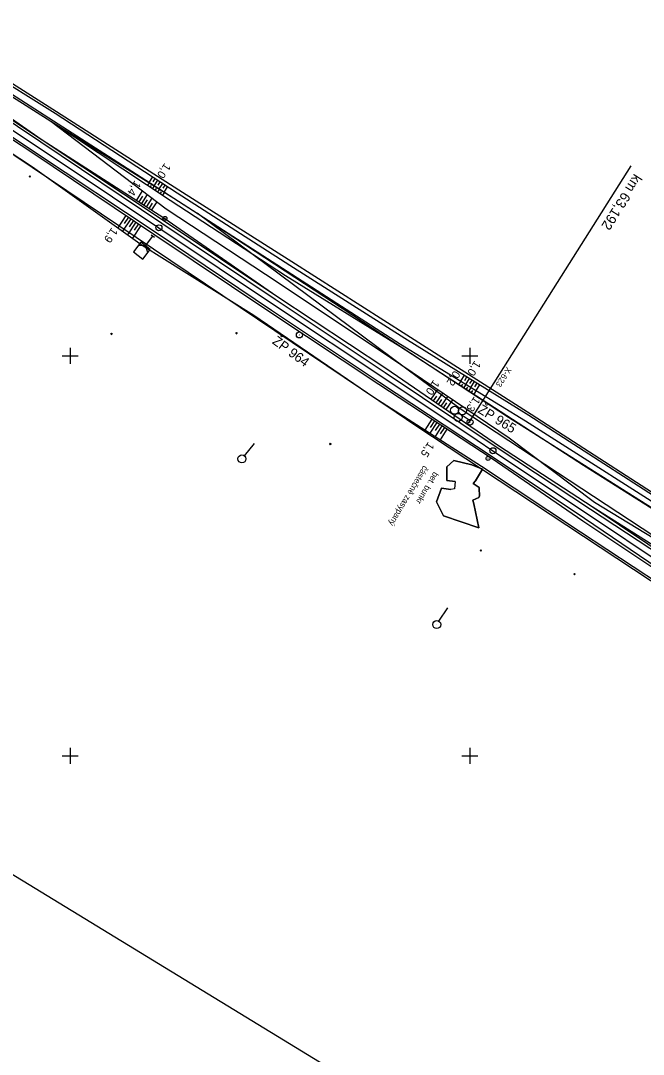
# Model space of a CAD drawing. Extents: x -804899 to -803847, y -1165742 to -1164942.
# Drawn here: x -804512.4 to -804356.6, y -1165474.6 to -1165216.2 of the extents above; entities that cross this region are included whole.
import ezdxf

# ---------------------------------------------------------------- set-up
doc = ezdxf.new("R2010")
doc.units = 0
for name, color, linetype in [('0381KM061-064P - Vrstva 1', 7, 'Continuous'), ('0381KM061-064P - Vrstva 23', 7, 'Continuous'), ('0381KM061-064P - Vrstva 36', 7, 'Continuous'), ('0381KM061-064P - Vrstva 4', 7, 'Continuous'), ('0381KM061-064P - Vrstva 48', 7, 'Continuous'), ('0381KM061-064P - Vrstva 49', 7, 'Continuous'), ('0381KM061-064P - Vrstva 51', 7, 'Continuous'), ('0381KM061-064P - Vrstva 55', 7, 'Continuous'), ('0381KM061-064P - Vrstva 7', 7, 'Continuous'), ('0381KM061-064P - Vrstva 8', 7, 'Continuous'), ('formát', 7, 'Continuous'), ('hran DP - hran DP', 7, 'Continuous'), ('krizky_1000 - Vrstva 1', 7, 'Continuous'), ('vyt_sit - stávající', 7, 'Continuous')]:
    doc.layers.add(name, color=color, linetype=linetype)

msp = doc.modelspace()

# ---------------------------------------------------------------- linework, layer by layer
at = {"layer": '0381KM061-064P - Vrstva 1'}
msp.add_lwpolyline([(-804619.36, -1165173.74), (-804594.78, -1165190.05), (-804577, -1165201.91), (-804561.16, -1165212.47), (-804538.32, -1165227.67), (-804515.3, -1165243.02), (-804489.41, -1165260.27), (-804477.81, -1165268), (-804447.6, -1165288.14), (-804422.03, -1165305.2), (-804398.19, -1165321.09), (-804394.24, -1165323.73), (-804371.85, -1165338.65), (-804349.9, -1165353.29), (-804326.64, -1165368.8), (-804303.84, -1165384.01), (-804280.33, -1165399.7), (-804257.04, -1165415.23), (-804233.85, -1165430.69)], dxfattribs=at)
at = {"layer": '0381KM061-064P - Vrstva 23'}
msp.add_lwpolyline([(-804404.03, -1165326.13), (-804405.8, -1165327.74), (-804405.76, -1165331.16), (-804403.73, -1165331.39), (-804403.83, -1165333.25), (-804404.81, -1165333.4), (-804407.08, -1165333.06), (-804408.38, -1165336.47), (-804406.6, -1165340), (-804397.73, -1165342.97), (-804399.04, -1165336.98), (-804399.28, -1165336.09), (-804397.81, -1165335.38), (-804397.64, -1165335), (-804397.65, -1165333.2), (-804397.7, -1165332.91), (-804399.15, -1165331.95), (-804398.58, -1165331.24), (-804396.84, -1165328.29), (-804399.49, -1165327.23), (-804404.03, -1165326.13)], dxfattribs=at)
at = {"layer": '0381KM061-064P - Vrstva 36'}
for p, q in [((-804456.41, -1165324.98), (-804453.88, -1165321.88)), ((-804457.04, -1165325.75), (-804457.04, -1165325.75)), ((-804407.75, -1165366.33), (-804405.5, -1165363.02)), ((-804408.31, -1165367.16), (-804408.31, -1165367.16))]:
    msp.add_line(p, q, dxfattribs=at)
for centre in [(-804457.04, -1165325.75), (-804408.31, -1165367.16)]:
    msp.add_circle(centre, 1, dxfattribs=at)
at = {"layer": '0381KM061-064P - Vrstva 4'}
for points in [[(-804755.73, -1165115.93), (-804748.17, -1165116.91), (-804721.25, -1165123.25), (-804698.66, -1165130.22), (-804681.33, -1165136.99), (-804671.47, -1165141.65), (-804648.84, -1165153.36), (-804638.11, -1165160.03), (-804624.48, -1165168.7), (-804602.56, -1165183.07), (-804574.47, -1165201.72), (-804542.72, -1165222.84), (-804507.36, -1165246.55), (-804477.08, -1165266.82), (-804448.75, -1165285.88), (-804421.18, -1165304.15), (-804392.89, -1165323.09), (-804369.85, -1165338.37), (-804348.86, -1165352.04), (-804325.13, -1165367.98), (-804299.32, -1165385.27), (-804266.05, -1165407.31), (-804234.28, -1165428.6)], [(-804755.73, -1165115.93), (-804748.03, -1165116.49), (-804721.05, -1165122.36), (-804698.44, -1165129.77), (-804680.98, -1165136.5), (-804671.21, -1165140.89), (-804648.42, -1165152.46), (-804637.55, -1165159.43), (-804624.04, -1165168.29), (-804602.25, -1165182.38), (-804573.74, -1165201.2), (-804542.46, -1165222.56), (-804507.06, -1165246.03), (-804476.47, -1165266.24), (-804448.31, -1165285.08), (-804421.02, -1165303.1), (-804392.59, -1165322.59), (-804369.41, -1165337.65), (-804348.68, -1165351.59), (-804324.76, -1165367.42), (-804298.9, -1165384.42), (-804265.65, -1165406.5), (-804234.05, -1165428.04)], [(-804626.64, -1165171.43), (-804605.18, -1165186.34), (-804576.91, -1165204.69), (-804544.69, -1165226.09), (-804509.35, -1165249.3), (-804478.87, -1165269.77), (-804450.06, -1165288.98), (-804422.82, -1165307.11), (-804394.42, -1165325.66), (-804371.77, -1165341.24), (-804350.46, -1165355.38), (-804326.73, -1165371.34), (-804301.47, -1165388.34), (-804268.3, -1165410.72), (-804235.74, -1165432.01)], [(-804576.36, -1165204.15), (-804544.19, -1165225.52), (-804508.95, -1165249), (-804478.52, -1165269.18), (-804449.67, -1165288.56), (-804422.62, -1165306.58), (-804394.22, -1165325.33), (-804371.37, -1165340.61), (-804350.54, -1165354.66), (-804326.31, -1165370.81), (-804300.9, -1165387.72), (-804267.8, -1165409.92), (-804235.52, -1165431.44)]]:
    msp.add_lwpolyline(points, dxfattribs=at)
at = {"layer": '0381KM061-064P - Vrstva 48'}
for p, q in [((-804480.29, -1165256.71), (-804479.34, -1165255.26)), ((-804479.28, -1165256.53), (-804478.71, -1165255.67)), ((-804479.02, -1165257.51), (-804478.08, -1165256.08)), ((-804478.01, -1165257.34), (-804477.46, -1165256.49)), ((-804481.97, -1165258.76), (-804483.45, -1165261.08)), ((-804480.25, -1165256.74), (-804480.67, -1165257.37)), ((-804479.78, -1165257.4), (-804480.04, -1165257.79)), ((-804478.97, -1165257.53), (-804479.42, -1165258.2)), ((-804478.52, -1165258.2), (-804478.79, -1165258.61)), ((-804477.7, -1165258.33), (-804478.16, -1165259.03)), ((-804477.74, -1165258.3), (-804476.83, -1165256.9)), ((-804477.25, -1165259.01), (-804477.54, -1165259.44)), ((-804476.43, -1165259.12), (-804476.91, -1165259.86)), ((-804476.74, -1165258.14), (-804476.2, -1165257.3)), ((-804476.47, -1165259.09), (-804475.57, -1165257.71)), ((-804481.95, -1165260.12), (-804482.82, -1165261.48)), ((-804480.77, -1165259.67), (-804482.18, -1165261.89)), ((-804480.72, -1165260.99), (-804481.55, -1165262.29)), ((-804479.57, -1165260.57), (-804480.92, -1165262.69)), ((-804478.37, -1165261.48), (-804479.66, -1165263.5)), ((-804479.5, -1165261.86), (-804480.29, -1165263.1)), ((-804486.06, -1165264.95), (-804488.11, -1165268)), ((-804484.82, -1165265.78), (-804486.89, -1165268.87)), ((-804485.44, -1165265.36), (-804486.47, -1165266.9)), ((-804483.57, -1165266.62), (-804485.67, -1165269.74)), ((-804484.19, -1165266.2), (-804485.24, -1165267.75)), ((-804482.32, -1165267.45), (-804484.45, -1165270.61)), ((-804482.95, -1165267.04), (-804484, -1165268.61)), ((-804402.3, -1165306.36), (-804401.37, -1165304.86)), ((-804401.29, -1165306.16), (-804400.73, -1165305.26)), ((-804401.02, -1165307.14), (-804400.09, -1165305.66)), ((-804402.31, -1165306.35), (-804402.82, -1165307.15)), ((-804401.88, -1165307.07), (-804402.19, -1165307.55)), ((-804401.03, -1165307.14), (-804401.56, -1165307.96)), ((-804400.6, -1165307.87), (-804400.93, -1165308.37)), ((-804399.75, -1165307.92), (-804400.3, -1165308.78)), ((-804400.01, -1165306.94), (-804399.46, -1165306.05)), ((-804399.74, -1165307.93), (-804398.82, -1165306.45)), ((-804398.73, -1165307.73), (-804398.18, -1165306.84)), ((-804398.46, -1165308.71), (-804397.55, -1165307.24)), ((-804409.69, -1165310.87), (-804408.04, -1165308.45)), ((-804409.07, -1165311.29), (-804408.24, -1165310.08)), ((-804408.45, -1165311.72), (-804406.79, -1165309.3)), ((-804407.22, -1165312.57), (-804405.55, -1165310.14)), ((-804399.33, -1165308.66), (-804399.67, -1165309.19)), ((-804398.47, -1165308.71), (-804399.04, -1165309.59)), ((-804407.84, -1165312.14), (-804407, -1165310.93)), ((-804406.6, -1165312.99), (-804405.76, -1165311.77)), ((-804405.98, -1165313.41), (-804404.31, -1165310.98)), ((-804411.18, -1165318.55), (-804409.42, -1165315.86)), ((-804409.92, -1165319.36), (-804408.16, -1165316.68)), ((-804409.84, -1165317.89), (-804408.79, -1165316.27)), ((-804408.65, -1165320.17), (-804406.91, -1165317.5)), ((-804408.58, -1165318.7), (-804407.54, -1165317.09)), ((-804407.39, -1165320.98), (-804405.65, -1165318.32)), ((-804407.32, -1165319.51), (-804406.28, -1165317.91))]:
    msp.add_line(p, q, dxfattribs=at)
at = {"layer": '0381KM061-064P - Vrstva 49'}
for p, q in [((-804509.94, -1165255.38), (-804510.3, -1165255.03)), ((-804509.94, -1165255.03), (-804510.3, -1165255.38)), ((-804489.49, -1165294.74), (-804489.84, -1165294.38)), ((-804489.49, -1165294.38), (-804489.84, -1165294.74)), ((-804458.23, -1165294.57), (-804458.58, -1165294.21)), ((-804458.23, -1165294.21), (-804458.58, -1165294.57)), ((-804434.74, -1165322.21), (-804435.09, -1165321.86)), ((-804434.74, -1165321.86), (-804435.09, -1165322.21)), ((-804397.06, -1165348.83), (-804397.41, -1165348.47)), ((-804397.06, -1165348.47), (-804397.41, -1165348.83)), ((-804373.68, -1165354.74), (-804374.04, -1165354.39)), ((-804373.68, -1165354.39), (-804374.04, -1165354.74))]:
    msp.add_line(p, q, dxfattribs=at)
for points in [[(-804668.09, -1165135.13), (-804646.08, -1165148.91), (-804635.34, -1165155.79), (-804621.98, -1165164.4), (-804599.68, -1165178.86), (-804570.23, -1165197.63), (-804539.04, -1165217.4), (-804503.79, -1165239.32), (-804473.21, -1165259.25), (-804445.02, -1165277.37), (-804416.3, -1165295.6), (-804385.23, -1165314.87), (-804342.84, -1165342.16), (-804322.16, -1165355.5), (-804292.15, -1165374.6), (-804262.58, -1165393.44), (-804234.25, -1165411.43)], [(-804668.53, -1165136.56), (-804646.51, -1165150.38), (-804635.75, -1165157.19), (-804622.88, -1165165.28), (-804600.74, -1165180), (-804571.06, -1165199.05), (-804539.91, -1165219.23), (-804504.85, -1165241.38), (-804474.07, -1165260.59), (-804445.75, -1165278.86), (-804417.38, -1165297.08), (-804386.13, -1165316.29), (-804343.68, -1165343.22), (-804323.05, -1165356.81), (-804293.41, -1165375.48), (-804263.45, -1165394.43), (-804234.68, -1165412.78)], [(-804651.73, -1165158.22), (-804641.24, -1165165.82), (-804629.21, -1165174.28), (-804606.38, -1165188.59), (-804578.69, -1165207.38), (-804546.55, -1165228.41), (-804509.4, -1165252.77), (-804482.02, -1165272.35), (-804454.07, -1165289.87), (-804424.02, -1165310.32)], [(-804621.79, -1165169), (-804602.1, -1165181.9), (-804573.29, -1165200.8), (-804541.65, -1165222.05), (-804507.06, -1165246.03), (-804476.55, -1165265.48), (-804448.31, -1165285.08)], [(-804576.91, -1165204.69), (-804544.69, -1165226.09), (-804509.35, -1165249.3), (-804478.87, -1165269.77), (-804450.06, -1165288.98), (-804422.82, -1165307.11), (-804394.42, -1165325.66), (-804371.77, -1165341.24), (-804350.46, -1165355.38), (-804326.73, -1165371.34), (-804301.47, -1165388.34), (-804268.3, -1165410.72), (-804235.74, -1165432.01)], [(-804504.85, -1165241.38), (-804475.98, -1165263.3)], [(-804504.85, -1165241.38), (-804474.97, -1165261.14)], [(-804474.97, -1165261.14), (-804446.16, -1165279.93), (-804417.55, -1165297.62), (-804371.56, -1165327.37), (-804344.89, -1165344.14), (-804323.3, -1165357.63), (-804293.83, -1165376.15), (-804263.84, -1165395.04), (-804235.23, -1165413.58)], [(-804475.98, -1165263.3), (-804448.01, -1165281.64), (-804419.88, -1165300.43), (-804390.2, -1165320.54), (-804368.79, -1165336.61), (-804347.55, -1165349.48), (-804323.92, -1165365.2), (-804298.45, -1165381.67), (-804264.49, -1165403.75), (-804232.5, -1165426.01)], [(-804448.31, -1165285.08), (-804421.02, -1165303.1), (-804392.59, -1165322.59), (-804369.41, -1165337.65)], [(-804424.02, -1165310.32), (-804397.08, -1165327.6), (-804372.3, -1165344.03), (-804352.55, -1165356.96), (-804329.59, -1165372.88)], [(-804403.73, -1165331.39), (-804405.76, -1165331.16), (-804405.8, -1165327.74), (-804404.03, -1165326.13), (-804399.49, -1165327.23), (-804396.84, -1165328.29), (-804398.58, -1165331.24)], [(-804403.73, -1165331.39), (-804403.83, -1165333.25), (-804404.81, -1165333.4)], [(-804398.58, -1165331.24), (-804399.15, -1165331.95), (-804397.7, -1165332.91), (-804397.65, -1165333.2), (-804397.64, -1165335), (-804397.81, -1165335.38), (-804399.28, -1165336.09), (-804399.04, -1165336.98)], [(-804399.04, -1165336.98), (-804397.73, -1165342.97), (-804406.6, -1165340), (-804408.38, -1165336.47), (-804407.08, -1165333.06), (-804404.81, -1165333.4)], [(-804369.41, -1165337.65), (-804350.13, -1165349.85)]]:
    msp.add_lwpolyline(points, dxfattribs=at)
at = {"layer": '0381KM061-064P - Vrstva 51'}
msp.add_lwpolyline([(-804728.9, -1165105.9), (-804711.54, -1165108.67), (-804704.35, -1165111.8), (-804683.69, -1165124.09), (-804676.95, -1165128.43), (-804667.36, -1165134.41), (-804645.71, -1165148.3), (-804634.7, -1165155.23), (-804621.63, -1165163.62), (-804599.19, -1165178.23), (-804569.67, -1165197.16), (-804538.42, -1165216.77), (-804503.41, -1165238.94), (-804472.82, -1165258.55), (-804444.57, -1165276.4), (-804415.82, -1165294.73), (-804384.7, -1165314.57), (-804342.59, -1165341.72), (-804321.8, -1165355.02), (-804291.77, -1165374.22), (-804262.45, -1165392.96)], dxfattribs=at)
at = {"layer": '0381KM061-064P - Vrstva 55'}
msp.add_lwpolyline([(-804468.27, -1165264.32), (-804426.86, -1165291.43), (-804390.35, -1165315.35), (-804348.41, -1165341.86), (-804327.45, -1165354.94), (-804302.94, -1165371.26), (-804261.01, -1165397.26), (-804213.5, -1165427.44), (-804191.69, -1165441.88), (-804177.28, -1165451.4), (-804169.73, -1165458.18), (-804172.29, -1165470.42), (-804193.11, -1165453.43), (-804217.51, -1165435.77), (-804323.51, -1165365.07), (-804402.46, -1165313.29)], close=True, dxfattribs=at)
at = {"layer": '0381KM061-064P - Vrstva 7'}
for p, q in [((-804476.35, -1165265.63), (-804476.26, -1165265.69)), ((-804481.17, -1165272.51), (-804479.35, -1165270.13)), ((-804478.95, -1165270.43), (-804479.75, -1165269.83)), ((-804395.51, -1165325.63), (-804395.43, -1165325.69))]:
    msp.add_line(p, q, dxfattribs=at)
for points in [[(-804481.17, -1165272.51), (-804482.36, -1165271.6), (-804484.18, -1165273.99), (-804481.8, -1165275.81), (-804479.98, -1165273.42), (-804481.17, -1165272.51)], [(-804480.59, -1165274.22), (-804481.17, -1165272.51), (-804482.97, -1165272.4)]]:
    msp.add_lwpolyline(points, dxfattribs=at)
for centre, radius in [((-804476.3, -1165265.66), 0.5), ((-804477.81, -1165268), 0.75), ((-804394.24, -1165323.73), 0.75), ((-804395.47, -1165325.66), 0.5)]:
    msp.add_circle(centre, radius, dxfattribs=at)
at = {"layer": '0381KM061-064P - Vrstva 8'}
for p, q in [((-804399.91, -1165316.21), (-804359.62, -1165252.51)), ((-804399.91, -1165316.21), (-804402.41, -1165314.55)), ((-804400.33, -1165316.84), (-804399.49, -1165315.59))]:
    msp.add_line(p, q, dxfattribs=at)
for centre in [(-804403.82, -1165313.61), (-804401.85, -1165313.72), (-804402.96, -1165315.38)]:
    msp.add_circle(centre, 1, dxfattribs=at)
at = {"layer": 'formát'}
msp.add_line((-804360.64, -1165523.44), (-804898.57, -1165195.52), dxfattribs=at)
at = {"layer": 'hran DP - hran DP'}
for p, q in [((-804418.46, -1165314.18), (-804552.85, -1165223.84)), ((-804519.76, -1165231.32), (-804468.27, -1165264.32)), ((-804468.27, -1165264.32), (-804426.86, -1165291.43)), ((-804426.86, -1165291.43), (-804390.35, -1165315.35)), ((-804413.53, -1165317.49), (-804418.46, -1165314.18)), ((-804390.35, -1165315.35), (-804348.41, -1165341.86)), ((-804272.3, -1165410.7), (-804413.53, -1165317.49))]:
    msp.add_line(p, q, dxfattribs=at)
at = {"layer": 'krizky_1000 - Vrstva 1'}
for points in [[(-804502, -1165300), (-804498, -1165300)], [(-804500, -1165298), (-804500, -1165302)], [(-804402, -1165300), (-804398, -1165300)], [(-804400, -1165298), (-804400, -1165302)], [(-804500, -1165398), (-804500, -1165402)], [(-804400, -1165398), (-804400, -1165402)], [(-804502, -1165400), (-804498, -1165400)], [(-804402, -1165400), (-804398, -1165400)]]:
    msp.add_lwpolyline(points, dxfattribs=at)
at = {"layer": 'vyt_sit - stávající'}
for p, q in [((-804442.7, -1165294.74), (-804442.61, -1165294.8)), ((-804399.99, -1165316.55), (-804399.91, -1165316.61))]:
    msp.add_line(p, q, dxfattribs=at)
for centre in [(-804442.66, -1165294.77), (-804399.95, -1165316.58)]:
    msp.add_circle(centre, 0.756, dxfattribs=at)

# ---------------------------------------------------------------- texts
at = {"layer": '0381KM061-064P - Vrstva 23'}
for s, p in [('částečně zasypaný', (-804411.6, -1165327.33)), ('bet. bunkr', (-804409.02, -1165328.87))]:
    msp.add_text(s, height=1.5, rotation=239.0639, dxfattribs=at).set_placement(p)
at = {"layer": '0381KM061-064P - Vrstva 48'}
for s, rotation, p in [('1,0', 236.9037, (-804476.36, -1165251.68)), ('1,4', 237.4781, (-804483.81, -1165256.02)), ('1,9', 236.1009, (-804489.6, -1165267.8)), ('1,0', 238.1936, (-804398.79, -1165301.06)), ('0,2', 237.1025, (-804403.93, -1165303.54)), ('1,0', 235.8765, (-804409.09, -1165305.87)), ('1,3', 235.5742, (-804398.89, -1165310.02)), ('1,5', 236.8458, (-804410.41, -1165321.38))]:
    msp.add_text(s, height=2, rotation=rotation, dxfattribs=at).set_placement(p)
at = {"layer": '0381KM061-064P - Vrstva 8'}
for s, height, rotation, p in [('km 63,192', 2.5, 237.6925, (-804358.88, -1165254.34)), ('X-623', 1.5, 237.6921, (-804390.75, -1165302.64))]:
    msp.add_text(s, height=height, rotation=rotation, dxfattribs=at).set_placement(p)
at = {"layer": 'vyt_sit - stávající'}
for s, rotation, p in [('ŽP 964', 323.5611, (-804449.64, -1165296.77)), ('ŽP 965', 328.5611, (-804398.21, -1165314.06))]:
    msp.add_text(s, height=2.4, rotation=rotation, dxfattribs=at).set_placement(p)

doc.saveas('drawing.dxf')
